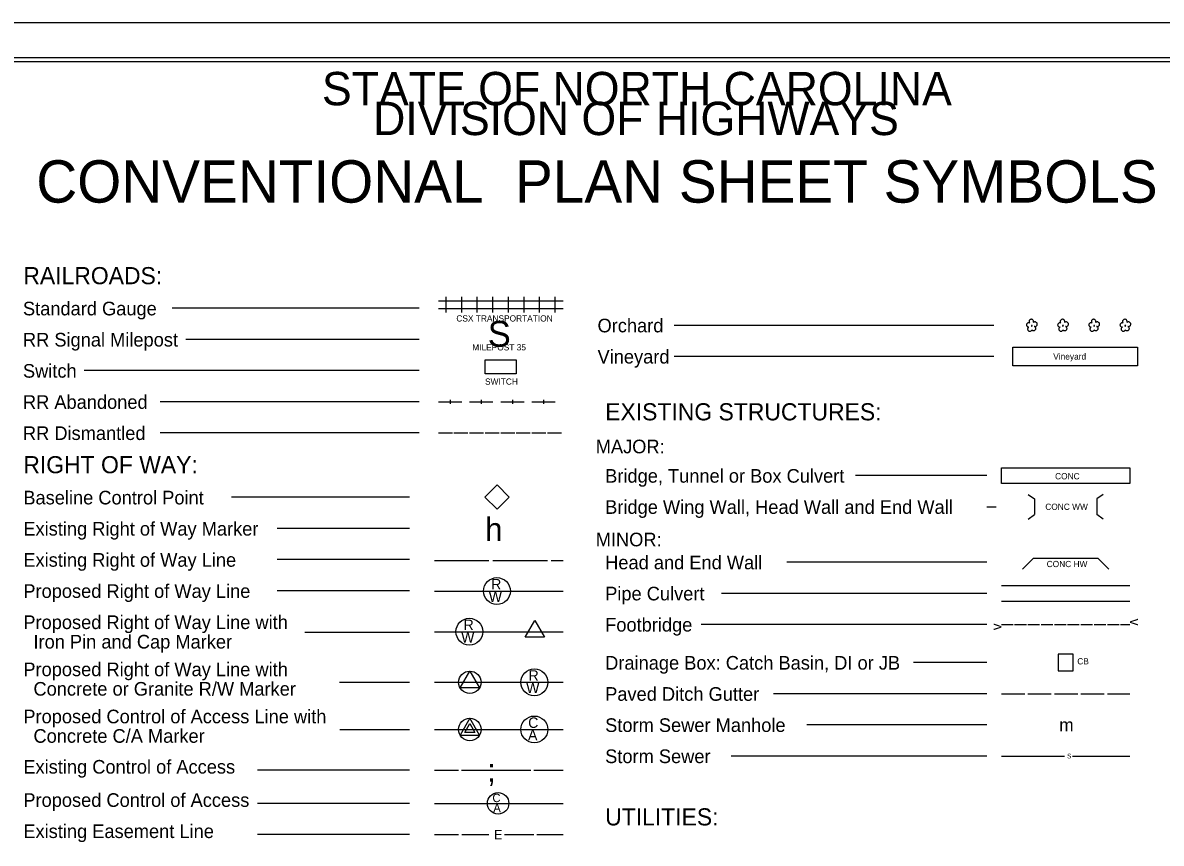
# Model space of a CAD drawing. Extents: x 573851.1 to 573884.7, y -53293.5 to -53271.5.
# Drawn here: x 573862.29 to 573876.9, y -53282.04 to -53271.51 of the extents above; entities that cross this region are included whole.
import ezdxf

# ---------------------------------------------------------------- set-up
doc = ezdxf.new("R2010")
doc.units = 0
for name, color, linetype in [('Default', 7, 'Continuous'), ('Sheet Cutting Line CELL', 7, 'Continuous'), ('Sheet Plot Border Inside CELL', 7, 'Continuous'), ('Sheet Plot Border Outside CELL', 7, 'Continuous'), ('Sheet Symbology CELL', 7, 'Continuous')]:
    doc.layers.add(name, color=color, linetype=linetype)

msp = doc.modelspace()

# ---------------------------------------------------------------- linework, layer by layer
at = {"layer": 'Default'}
msp.add_lwpolyline([(573868.221, -53277.599), (573868.378, -53277.442), (573868.534, -53277.599), (573868.378, -53277.755)], close=True, dxfattribs=at)
at = {"layer": 'Sheet Cutting Line CELL'}
msp.add_line((573884.745, -53271.51), (573851.065, -53271.51), dxfattribs=at)
at = {"layer": 'Sheet Plot Border Inside CELL'}
msp.add_lwpolyline([(573851.325, -53293.061), (573884.655, -53293.061), (573884.655, -53271.959), (573851.325, -53271.959)], close=True, dxfattribs=at)
at = {"layer": 'Sheet Plot Border Outside CELL'}
msp.add_lwpolyline([(573851.065, -53293.51), (573884.745, -53293.51), (573884.745, -53271.51), (573851.065, -53271.51)], close=True, dxfattribs=at)
at = {"layer": 'Sheet Symbology CELL'}
for p, q in [((573867.625, -53275.08), (573867.825, -53275.08)), ((573867.725, -53275.23), (573867.725, -53275.03)), ((573867.825, -53275.08), (573868.025, -53275.08)), ((573867.925, -53275.23), (573867.925, -53275.03)), ((573868.025, -53275.08), (573868.225, -53275.08)), ((573868.125, -53275.23), (573868.125, -53275.03)), ((573868.225, -53275.08), (573868.425, -53275.08)), ((573868.325, -53275.23), (573868.325, -53275.03)), ((573868.425, -53275.08), (573868.625, -53275.08)), ((573868.525, -53275.23), (573868.525, -53275.03)), ((573868.625, -53275.08), (573868.825, -53275.08)), ((573868.725, -53275.23), (573868.725, -53275.03)), ((573868.825, -53275.08), (573869.025, -53275.08)), ((573868.925, -53275.23), (573868.925, -53275.03)), ((573869.025, -53275.08), (573869.225, -53275.08)), ((573869.125, -53275.23), (573869.125, -53275.03)), ((573867.377, -53275.175), (573864.209, -53275.175)), ((573867.625, -53275.18), (573867.825, -53275.18)), ((573867.825, -53275.18), (573868.025, -53275.18)), ((573868.025, -53275.18), (573868.225, -53275.18)), ((573868.225, -53275.18), (573868.425, -53275.18)), ((573868.425, -53275.18), (573868.625, -53275.18)), ((573868.625, -53275.18), (573868.825, -53275.18)), ((573868.825, -53275.18), (573869.025, -53275.18)), ((573869.025, -53275.18), (573869.225, -53275.18)), ((573874.752, -53275.394), (573870.653, -53275.394)), ((573867.377, -53275.575), (573864.386, -53275.575)), ((573874.752, -53275.794), (573870.653, -53275.794)), ((573867.377, -53275.975), (573863.079, -53275.975)), ((573867.377, -53276.375), (573864.054, -53276.375)), ((573867.625, -53276.375), (573867.925, -53276.375)), ((573867.775, -53276.35), (573867.775, -53276.4)), ((573868.025, -53276.375), (573868.325, -53276.375)), ((573868.175, -53276.35), (573868.175, -53276.4)), ((573868.425, -53276.375), (573868.725, -53276.375)), ((573868.575, -53276.35), (573868.575, -53276.4)), ((573868.825, -53276.375), (573869.125, -53276.375)), ((573868.975, -53276.35), (573868.975, -53276.4)), ((573867.377, -53276.775), (573864.054, -53276.775)), ((573867.377, -53276.775), (573864.054, -53276.775)), ((573867.625, -53276.775), (573867.805, -53276.775)), ((573867.825, -53276.775), (573868.005, -53276.775)), ((573868.025, -53276.775), (573868.205, -53276.775)), ((573868.225, -53276.775), (573868.405, -53276.775)), ((573868.425, -53276.775), (573868.605, -53276.775)), ((573868.625, -53276.775), (573868.805, -53276.775)), ((573868.825, -53276.775), (573869.005, -53276.775)), ((573869.025, -53276.775), (573869.205, -53276.775)), ((573874.665, -53277.323), (573872.977, -53277.323)), ((573875.194, -53277.566), (573875.276, -53277.623)), ((573876.158, -53277.566), (573876.076, -53277.623)), ((573867.254, -53277.602), (573864.97, -53277.602)), ((573874.665, -53277.723), (573874.785, -53277.723)), ((573875.276, -53277.623), (573875.276, -53277.823)), ((573876.076, -53277.623), (573876.076, -53277.823)), ((573875.194, -53277.881), (573875.276, -53277.823)), ((573876.158, -53277.881), (573876.076, -53277.823)), ((573867.254, -53278.002), (573865.556, -53278.002)), ((573867.254, -53278.402), (573865.556, -53278.402)), ((573867.575, -53278.414), (573868.275, -53278.414)), ((573868.325, -53278.414), (573869.025, -53278.414)), ((573869.075, -53278.414), (573869.225, -53278.414)), ((573874.665, -53278.435), (573872.099, -53278.435)), ((573875.122, -53278.526), (573875.264, -53278.385)), ((573875.264, -53278.385), (573876.089, -53278.385)), ((573876.089, -53278.385), (573876.23, -53278.526)), ((573874.851, -53278.735), (573876.501, -53278.735)), ((573867.254, -53278.802), (573865.556, -53278.802)), ((573867.575, -53278.805), (573869.225, -53278.805)), ((573874.665, -53278.835), (573871.261, -53278.835)), ((573874.851, -53278.935), (573876.501, -53278.935)), ((573867.575, -53279.327), (573869.225, -53279.327)), ((573868.864, -53279.327), (573868.864, -53279.327)), ((573874.665, -53279.235), (573870.996, -53279.235)), ((573874.851, -53279.235), (573875.001, -53279.235)), ((573875.021, -53279.235), (573875.171, -53279.235)), ((573875.191, -53279.235), (573875.341, -53279.235)), ((573875.361, -53279.235), (573875.511, -53279.235)), ((573875.531, -53279.235), (573875.681, -53279.235)), ((573875.701, -53279.235), (573875.851, -53279.235)), ((573875.871, -53279.235), (573876.021, -53279.235)), ((573876.041, -53279.235), (573876.191, -53279.235)), ((573876.211, -53279.235), (573876.361, -53279.235)), ((573876.381, -53279.235), (573876.501, -53279.235)), ((573867.254, -53279.339), (573865.912, -53279.339)), ((573874.665, -53279.723), (573873.721, -53279.723)), ((573867.254, -53279.98), (573866.355, -53279.98)), ((573867.575, -53279.977), (573869.225, -53279.977)), ((573868.029, -53279.977), (573868.029, -53279.977)), ((573874.665, -53280.123), (573871.926, -53280.123)), ((573874.851, -53280.123), (573875.151, -53280.123)), ((573875.191, -53280.123), (573875.491, -53280.123)), ((573875.531, -53280.123), (573875.831, -53280.123)), ((573875.871, -53280.123), (573876.171, -53280.123)), ((573876.211, -53280.123), (573876.501, -53280.123)), ((573867.254, -53280.585), (573866.362, -53280.585)), ((573867.575, -53280.582), (573869.225, -53280.582)), ((573868.029, -53280.582), (573868.029, -53280.582)), ((573874.665, -53280.523), (573872.352, -53280.523)), ((573874.665, -53280.923), (573871.381, -53280.923)), ((573874.851, -53280.923), (573875.662, -53280.923)), ((573875.762, -53280.923), (573876.501, -53280.923)), ((573867.254, -53281.104), (573865.303, -53281.104)), ((573867.575, -53281.104), (573867.884, -53281.104)), ((573867.924, -53281.104), (573868.812, -53281.104)), ((573868.852, -53281.104), (573869.225, -53281.104)), ((573867.254, -53281.531), (573865.303, -53281.531)), ((573867.575, -53281.531), (573869.225, -53281.531)), ((573867.254, -53281.931), (573865.303, -53281.931)), ((573867.575, -53281.931), (573867.885, -53281.931)), ((573867.925, -53281.931), (573868.275, -53281.931)), ((573868.475, -53281.931), (573868.85, -53281.931)), ((573868.89, -53281.931), (573869.225, -53281.931))]:
    msp.add_line(p, q, dxfattribs=at)
for points in [[(573884.405, -53272.01), (573854.405, -53272.01), (573854.405, -53292.989), (573884.405, -53292.989)], [(573868.225, -53275.836), (573868.625, -53275.836), (573868.625, -53276.018), (573868.225, -53276.018)], [(573868.739, -53279.399), (573868.864, -53279.183), (573868.989, -53279.399)], [(573875.58, -53279.83), (573875.772, -53279.83), (573875.772, -53279.617), (573875.58, -53279.617)], [(573867.904, -53280.049), (573868.029, -53279.833), (573868.154, -53280.049)], [(573867.904, -53280.654), (573868.154, -53280.654), (573868.029, -53280.438)], [(573867.964, -53280.62), (573868.029, -53280.507), (573868.094, -53280.62)]]:
    msp.add_lwpolyline(points, close=True, dxfattribs=at)
for points in [[(573875.26, -53275.359), (573875.263, -53275.353), (573875.264, -53275.347), (573875.263, -53275.341), (573875.262, -53275.335), (573875.259, -53275.33), (573875.256, -53275.325), (573875.251, -53275.321), (573875.246, -53275.318), (573875.239, -53275.316), (573875.234, -53275.316), (573875.228, -53275.317), (573875.222, -53275.319), (573875.217, -53275.322), (573875.212, -53275.326), (573875.209, -53275.332), (573875.207, -53275.337), (573875.206, -53275.343), (573875.206, -53275.349), (573875.207, -53275.355), (573875.21, -53275.36), (573875.214, -53275.366), (573875.209, -53275.363), (573875.203, -53275.362), (573875.197, -53275.362), (573875.192, -53275.364), (573875.187, -53275.366), (573875.182, -53275.37), (573875.178, -53275.374), (573875.175, -53275.379), (573875.174, -53275.384), (573875.173, -53275.391), (573875.174, -53275.396), (573875.176, -53275.401), (573875.18, -53275.406), (573875.183, -53275.41), (573875.188, -53275.413), (573875.194, -53275.416), (573875.199, -53275.417), (573875.205, -53275.417), (573875.2, -53275.419), (573875.195, -53275.423), (573875.192, -53275.427), (573875.19, -53275.433), (573875.188, -53275.439), (573875.188, -53275.444), (573875.189, -53275.45), (573875.192, -53275.455), (573875.195, -53275.46), (573875.199, -53275.464), (573875.204, -53275.467), (573875.209, -53275.469), (573875.215, -53275.469), (573875.221, -53275.469), (573875.226, -53275.468), (573875.231, -53275.464), (573875.236, -53275.461), (573875.241, -53275.452)], [(573875.241, -53275.452), (573875.253, -53275.459), (573875.259, -53275.461), (573875.265, -53275.462), (573875.271, -53275.461), (573875.276, -53275.459), (573875.281, -53275.456), (573875.286, -53275.452), (573875.289, -53275.447), (573875.291, -53275.442), (573875.293, -53275.436), (573875.292, -53275.43), (573875.291, -53275.424), (573875.287, -53275.418), (573875.284, -53275.414), (573875.279, -53275.411), (573875.273, -53275.408), (573875.279, -53275.409), (573875.286, -53275.409), (573875.291, -53275.407), (573875.297, -53275.404), (573875.302, -53275.401), (573875.306, -53275.396), (573875.309, -53275.39), (573875.31, -53275.384), (573875.311, -53275.378), (573875.31, -53275.372), (573875.308, -53275.366), (573875.304, -53275.361), (573875.299, -53275.356), (573875.294, -53275.353), (573875.288, -53275.351), (573875.282, -53275.35), (573875.276, -53275.35), (573875.27, -53275.352), (573875.265, -53275.355), (573875.26, -53275.359)], [(573875.66, -53275.359), (573875.663, -53275.353), (573875.664, -53275.347), (573875.663, -53275.341), (573875.662, -53275.335), (573875.659, -53275.33), (573875.656, -53275.325), (573875.651, -53275.321), (573875.646, -53275.318), (573875.639, -53275.316), (573875.634, -53275.316), (573875.628, -53275.317), (573875.622, -53275.319), (573875.617, -53275.322), (573875.612, -53275.326), (573875.609, -53275.332), (573875.607, -53275.337), (573875.606, -53275.343), (573875.606, -53275.349), (573875.607, -53275.355), (573875.61, -53275.36), (573875.614, -53275.366), (573875.609, -53275.363), (573875.603, -53275.362), (573875.597, -53275.362), (573875.592, -53275.364), (573875.587, -53275.366), (573875.582, -53275.37), (573875.578, -53275.374), (573875.575, -53275.379), (573875.574, -53275.384), (573875.573, -53275.391), (573875.574, -53275.396), (573875.576, -53275.401), (573875.58, -53275.406), (573875.583, -53275.41), (573875.588, -53275.413), (573875.594, -53275.416), (573875.599, -53275.417), (573875.605, -53275.417), (573875.6, -53275.419), (573875.595, -53275.423), (573875.592, -53275.427), (573875.59, -53275.433), (573875.588, -53275.439), (573875.588, -53275.444), (573875.589, -53275.45), (573875.592, -53275.455), (573875.595, -53275.46), (573875.599, -53275.464), (573875.604, -53275.467), (573875.609, -53275.469), (573875.615, -53275.469), (573875.621, -53275.469), (573875.626, -53275.468), (573875.631, -53275.464), (573875.636, -53275.461), (573875.641, -53275.452)], [(573875.641, -53275.452), (573875.653, -53275.459), (573875.659, -53275.461), (573875.665, -53275.462), (573875.671, -53275.461), (573875.676, -53275.459), (573875.681, -53275.456), (573875.686, -53275.452), (573875.689, -53275.447), (573875.691, -53275.442), (573875.693, -53275.436), (573875.692, -53275.43), (573875.691, -53275.424), (573875.687, -53275.418), (573875.684, -53275.414), (573875.679, -53275.411), (573875.673, -53275.408), (573875.679, -53275.409), (573875.686, -53275.409), (573875.691, -53275.407), (573875.697, -53275.404), (573875.702, -53275.401), (573875.706, -53275.396), (573875.709, -53275.39), (573875.71, -53275.384), (573875.711, -53275.378), (573875.71, -53275.372), (573875.708, -53275.366), (573875.704, -53275.361), (573875.699, -53275.356), (573875.694, -53275.353), (573875.688, -53275.351), (573875.682, -53275.35), (573875.676, -53275.35), (573875.67, -53275.352), (573875.665, -53275.355), (573875.66, -53275.359)], [(573876.06, -53275.359), (573876.063, -53275.353), (573876.064, -53275.347), (573876.063, -53275.341), (573876.062, -53275.335), (573876.059, -53275.33), (573876.056, -53275.325), (573876.051, -53275.321), (573876.046, -53275.318), (573876.039, -53275.316), (573876.034, -53275.316), (573876.028, -53275.317), (573876.022, -53275.319), (573876.017, -53275.322), (573876.012, -53275.326), (573876.009, -53275.332), (573876.007, -53275.337), (573876.006, -53275.343), (573876.006, -53275.349), (573876.007, -53275.355), (573876.01, -53275.36), (573876.014, -53275.366), (573876.009, -53275.363), (573876.003, -53275.362), (573875.997, -53275.362), (573875.992, -53275.364), (573875.987, -53275.366), (573875.982, -53275.37), (573875.978, -53275.374), (573875.975, -53275.379), (573875.974, -53275.384), (573875.973, -53275.391), (573875.974, -53275.396), (573875.976, -53275.401), (573875.98, -53275.406), (573875.983, -53275.41), (573875.988, -53275.413), (573875.994, -53275.416), (573875.999, -53275.417), (573876.005, -53275.417), (573876, -53275.419), (573875.995, -53275.423), (573875.992, -53275.427), (573875.99, -53275.433), (573875.988, -53275.439), (573875.988, -53275.444), (573875.989, -53275.45), (573875.992, -53275.455), (573875.995, -53275.46), (573875.999, -53275.464), (573876.004, -53275.467), (573876.009, -53275.469), (573876.015, -53275.469), (573876.021, -53275.469), (573876.026, -53275.468), (573876.031, -53275.464), (573876.036, -53275.461), (573876.041, -53275.452)], [(573876.041, -53275.452), (573876.053, -53275.459), (573876.059, -53275.461), (573876.065, -53275.462), (573876.071, -53275.461), (573876.076, -53275.459), (573876.081, -53275.456), (573876.086, -53275.452), (573876.089, -53275.447), (573876.091, -53275.442), (573876.093, -53275.436), (573876.092, -53275.43), (573876.091, -53275.424), (573876.087, -53275.418), (573876.084, -53275.414), (573876.079, -53275.411), (573876.073, -53275.408), (573876.079, -53275.409), (573876.086, -53275.409), (573876.091, -53275.407), (573876.097, -53275.404), (573876.102, -53275.401), (573876.106, -53275.396), (573876.109, -53275.39), (573876.11, -53275.384), (573876.111, -53275.378), (573876.11, -53275.372), (573876.108, -53275.366), (573876.104, -53275.361), (573876.099, -53275.356), (573876.094, -53275.353), (573876.088, -53275.351), (573876.082, -53275.35), (573876.076, -53275.35), (573876.07, -53275.352), (573876.065, -53275.355), (573876.06, -53275.359)], [(573876.46, -53275.359), (573876.463, -53275.353), (573876.464, -53275.347), (573876.463, -53275.341), (573876.462, -53275.335), (573876.459, -53275.33), (573876.456, -53275.325), (573876.451, -53275.321), (573876.446, -53275.318), (573876.439, -53275.316), (573876.434, -53275.316), (573876.428, -53275.317), (573876.422, -53275.319), (573876.417, -53275.322), (573876.412, -53275.326), (573876.409, -53275.332), (573876.407, -53275.337), (573876.406, -53275.343), (573876.406, -53275.349), (573876.407, -53275.355), (573876.41, -53275.36), (573876.414, -53275.366), (573876.409, -53275.363), (573876.403, -53275.362), (573876.397, -53275.362), (573876.392, -53275.364), (573876.387, -53275.366), (573876.382, -53275.37), (573876.378, -53275.374), (573876.375, -53275.379), (573876.374, -53275.384), (573876.373, -53275.391), (573876.374, -53275.396), (573876.376, -53275.401), (573876.38, -53275.406), (573876.383, -53275.41), (573876.388, -53275.413), (573876.394, -53275.416), (573876.399, -53275.417), (573876.405, -53275.417), (573876.4, -53275.419), (573876.395, -53275.423), (573876.392, -53275.427), (573876.39, -53275.433), (573876.388, -53275.439), (573876.388, -53275.444), (573876.389, -53275.45), (573876.392, -53275.455), (573876.395, -53275.46), (573876.399, -53275.464), (573876.404, -53275.467), (573876.409, -53275.469), (573876.415, -53275.469), (573876.421, -53275.469), (573876.426, -53275.468), (573876.431, -53275.464), (573876.436, -53275.461), (573876.441, -53275.452)], [(573876.441, -53275.452), (573876.453, -53275.459), (573876.459, -53275.461), (573876.465, -53275.462), (573876.471, -53275.461), (573876.476, -53275.459), (573876.481, -53275.456), (573876.486, -53275.452), (573876.489, -53275.447), (573876.491, -53275.442), (573876.493, -53275.436), (573876.492, -53275.43), (573876.491, -53275.424), (573876.487, -53275.418), (573876.484, -53275.414), (573876.479, -53275.411), (573876.473, -53275.408), (573876.479, -53275.409), (573876.486, -53275.409), (573876.491, -53275.407), (573876.497, -53275.404), (573876.502, -53275.401), (573876.506, -53275.396), (573876.509, -53275.39), (573876.51, -53275.384), (573876.511, -53275.378), (573876.51, -53275.372), (573876.508, -53275.366), (573876.504, -53275.361), (573876.499, -53275.356), (573876.494, -53275.353), (573876.488, -53275.351), (573876.482, -53275.35), (573876.476, -53275.35), (573876.47, -53275.352), (573876.465, -53275.355), (573876.46, -53275.359)], [(573875.243, -53275.394), (573875.24, -53275.394), (573875.238, -53275.395), (573875.236, -53275.396), (573875.236, -53275.399), (573875.236, -53275.401), (573875.238, -53275.403), (573875.241, -53275.403), (573875.243, -53275.403), (573875.245, -53275.401), (573875.246, -53275.398), (573875.245, -53275.396), (573875.243, -53275.394)], [(573875.643, -53275.394), (573875.64, -53275.394), (573875.638, -53275.395), (573875.636, -53275.396), (573875.636, -53275.399), (573875.636, -53275.401), (573875.638, -53275.403), (573875.641, -53275.403), (573875.643, -53275.403), (573875.645, -53275.401), (573875.646, -53275.398), (573875.645, -53275.396), (573875.643, -53275.394)], [(573876.043, -53275.394), (573876.04, -53275.394), (573876.038, -53275.395), (573876.036, -53275.396), (573876.036, -53275.399), (573876.036, -53275.401), (573876.038, -53275.403), (573876.041, -53275.403), (573876.043, -53275.403), (573876.045, -53275.401), (573876.046, -53275.398), (573876.045, -53275.396), (573876.043, -53275.394)], [(573876.443, -53275.394), (573876.44, -53275.394), (573876.438, -53275.395), (573876.436, -53275.396), (573876.436, -53275.399), (573876.436, -53275.401), (573876.438, -53275.403), (573876.441, -53275.403), (573876.443, -53275.403), (573876.445, -53275.401), (573876.446, -53275.398), (573876.445, -53275.396), (573876.443, -53275.394)], [(573874.999, -53275.674), (573876.599, -53275.674), (573876.599, -53275.914), (573874.999, -53275.914), (573874.999, -53275.674)], [(573874.851, -53277.223), (573876.501, -53277.223), (573876.501, -53277.423), (573874.851, -53277.423), (573874.851, -53277.223)]]:
    msp.add_lwpolyline(points, dxfattribs=at)
for centre, radius in [((573868.377, -53278.805), 0.172), ((573868.023, -53279.327), 0.172), ((573868.029, -53279.977), 0.144), ((573868.857, -53279.977), 0.172), ((573868.029, -53280.582), 0.144), ((573868.857, -53280.582), 0.172), ((573868.392, -53281.531), 0.138)]:
    msp.add_circle(centre, radius, dxfattribs=at)

# ---------------------------------------------------------------- texts
for s, height, p in [('STATE OF NORTH CAROLINA', 0.42838, (573866.131, -53272.569)), ('DIVISION OF HIGHWAYS', 0.42838, (573866.788, -53272.952)), ('CONVENTIONAL  PLAN SHEET SYMBOLS', 0.54401, (573862.465, -53273.819)), ('RAILROADS:', 0.22, (573862.299, -53274.866)), ('Standard Gauge', 0.175, (573862.294, -53275.266)), ('S', 0.33, (573868.26, -53275.668)), ('Orchard', 0.175, (573869.668, -53275.484)), ('RR Signal Milepost', 0.175, (573862.294, -53275.666)), ('Vineyard', 0.175, (573869.668, -53275.884)), ('Switch', 0.175, (573862.294, -53276.066)), ('RR Abandoned', 0.175, (573862.294, -53276.466)), ('EXISTING STRUCTURES:', 0.22, (573869.766, -53276.614)), ('RR Dismantled', 0.175, (573862.294, -53276.866)), ('MAJOR:', 0.175, (573869.645, -53277.037)), ('RIGHT OF WAY:', 0.22, (573862.299, -53277.293)), ('Bridge, Tunnel or Box Culvert', 0.175, (573869.766, -53277.414)), ('CONC', 0.08, (573875.54, -53277.371)), ('Baseline Control Point', 0.175, (573862.299, -53277.693)), ('Bridge Wing Wall, Head Wall and End Wall', 0.175, (573869.766, -53277.814)), ('h', 0.3, (573868.225, -53278.164)), ('Existing Right of Way Marker', 0.175, (573862.299, -53278.093)), ('MINOR:', 0.175, (573869.645, -53278.231)), ('Existing Right of Way Line', 0.175, (573862.299, -53278.493)), ('Head and End Wall', 0.175, (573869.766, -53278.526)), ('Proposed Right of Way Line', 0.175, (573862.299, -53278.893)), ('R', 0.135, (573868.303, -53278.785)), ('Pipe Culvert', 0.175, (573869.766, -53278.925)), ('W', 0.135, (573868.272, -53278.944)), ('Proposed Right of Way Line with', 0.175, (573862.299, -53279.293)), ('R', 0.135, (573867.949, -53279.307)), ('Footbridge', 0.175, (573869.766, -53279.325)), ('W', 0.135, (573867.918, -53279.466)), ('  Iron Pin and Cap Marker', 0.175, (573862.299, -53279.543)), ('Drainage Box: Catch Basin, DI or JB', 0.175, (573869.766, -53279.814)), ('Proposed Right of Way Line with', 0.175, (573862.299, -53279.898)), ('R', 0.135, (573868.783, -53279.957)), ('  Concrete or Granite R/W Marker', 0.175, (573862.299, -53280.148)), ('W', 0.135, (573868.752, -53280.116)), ('Paved Ditch Gutter', 0.175, (573869.766, -53280.214)), ('Proposed Control of Access Line with', 0.175, (573862.299, -53280.503)), ('C', 0.135, (573868.778, -53280.562)), ('Storm Sewer Manhole', 0.175, (573869.766, -53280.614)), ('m', 0.165, (573875.594, -53280.606)), ('  Concrete C/A Marker', 0.175, (573862.299, -53280.753)), ('A', 0.135, (573868.776, -53280.721)), ('Storm Sewer', 0.175, (573869.766, -53281.014)), ('S', 0.06, (573875.694, -53280.953)), ('Existing Control of Access', 0.175, (573862.299, -53281.149)), (';', 0.3, (573868.25, -53281.254)), ('Proposed Control of Access', 0.175, (573862.299, -53281.576)), ('C', 0.108, (573868.319, -53281.515)), ('A', 0.108, (573868.33, -53281.644)), ('UTILITIES:', 0.22, (573869.766, -53281.814)), ('Existing Easement Line', 0.175, (573862.299, -53281.976)), ('E', 0.12, (573868.339, -53281.991))]:
    msp.add_text(s, height=height, dxfattribs=at).set_placement(p)
for s, height, rotation, p in [('CSX TRANSPORTATION', 0.08, 360, (573867.856, -53275.345)), ('MILEPOST 35', 0.08, 360, (573868.06, -53275.716)), ('Vineyard', 0.08, 0, (573875.516, -53275.834)), ('SWITCH', 0.08, 360, (573868.224, -53276.156)), ('CONC WW', 0.08, 0, (573875.414, -53277.763)), ('CONC HW', 0.08, 360, (573875.432, -53278.498)), ('v', 0.132, 270.2409, (573876.501, -53279.16)), ('v', 0.132, 89.7591, (573874.851, -53279.309)), ('CB', 0.08, 360, (573875.825, -53279.747))]:
    msp.add_text(s, height=height, rotation=rotation, dxfattribs=at).set_placement(p)

doc.saveas('drawing.dxf')
